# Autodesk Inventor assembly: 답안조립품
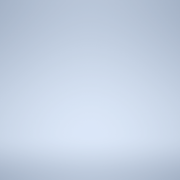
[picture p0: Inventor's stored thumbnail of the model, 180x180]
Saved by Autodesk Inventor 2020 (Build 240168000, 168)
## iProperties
Created: 2023-12
Part Number: 답안조립품
Document SubType Name: Assembly
Designer: oem
Author: oem
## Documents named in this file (1)
- C:\Users\oem\Desktop\731208V1015\답안조립품.iam
